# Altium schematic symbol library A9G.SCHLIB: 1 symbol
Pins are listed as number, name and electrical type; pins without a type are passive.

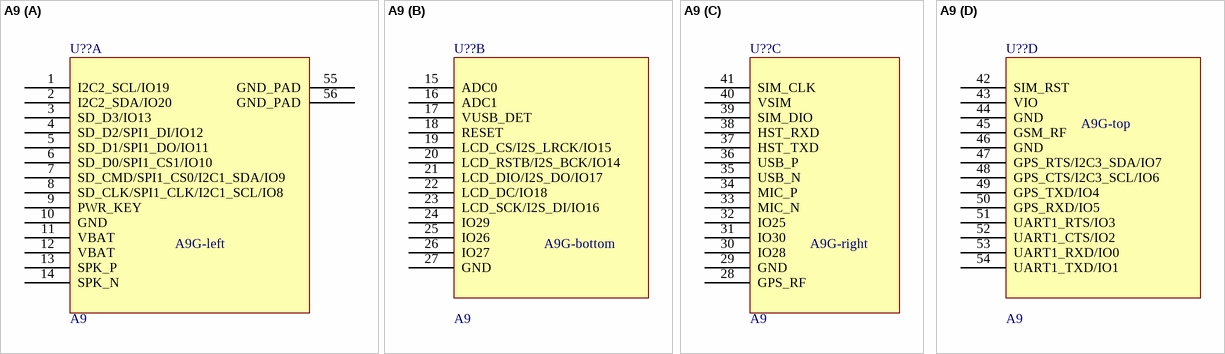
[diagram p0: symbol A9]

## A9
designator U??
footprint A9
part A pins: 1 I2C2_SCL/IO19, 2 I2C2_SDA/IO20, 3 SD_D3/IO13, 4 SD_D2/SPI1_DI/IO12, 5 SD_D1/SPI1_DO/IO11, 6 SD_D0/SPI1_CS1/IO10, 7 SD_CMD/SPI1_CS0/I2C1_SDA/IO9, 8 SD_CLK/SPI1_CLK/I2C1_SCL/IO8, 9 PWR_KEY, 10 GND, 11 VBAT, 12 VBAT, 13 SPK_P, 14 SPK_N, 55 GND_PAD, 56 GND_PAD
part B pins: 15 ADC0, 16 ADC1, 17 VUSB_DET, 18 RESET, 19 LCD_CS/I2S_LRCK/IO15, 20 LCD_RSTB/I2S_BCK/IO14, 21 LCD_DIO/I2S_DO/IO17, 22 LCD_DC/IO18, 23 LCD_SCK/I2S_DI/IO16, 24 IO29, 25 IO26, 26 IO27, 27 GND
part C pins: 28 GPS_RF, 29 GND, 30 IO28, 31 IO30, 32 IO25, 33 MIC_N, 34 MIC_P, 35 USB_N, 36 USB_P, 37 HST_TXD, 38 HST_RXD, 39 SIM_DIO, 40 VSIM, 41 SIM_CLK
part D pins: 42 SIM_RST, 43 VIO, 44 GND, 45 GSM_RF, 46 GND, 47 GPS_RTS/I2C3_SDA/IO7, 48 GPS_CTS/I2C3_SCL/IO6, 49 GPS_TXD/IO4, 50 GPS_RXD/IO5, 51 UART1_RTS/IO3, 52 UART1_CTS/IO2, 53 UART1_RXD/IO0, 54 UART1_TXD/IO1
